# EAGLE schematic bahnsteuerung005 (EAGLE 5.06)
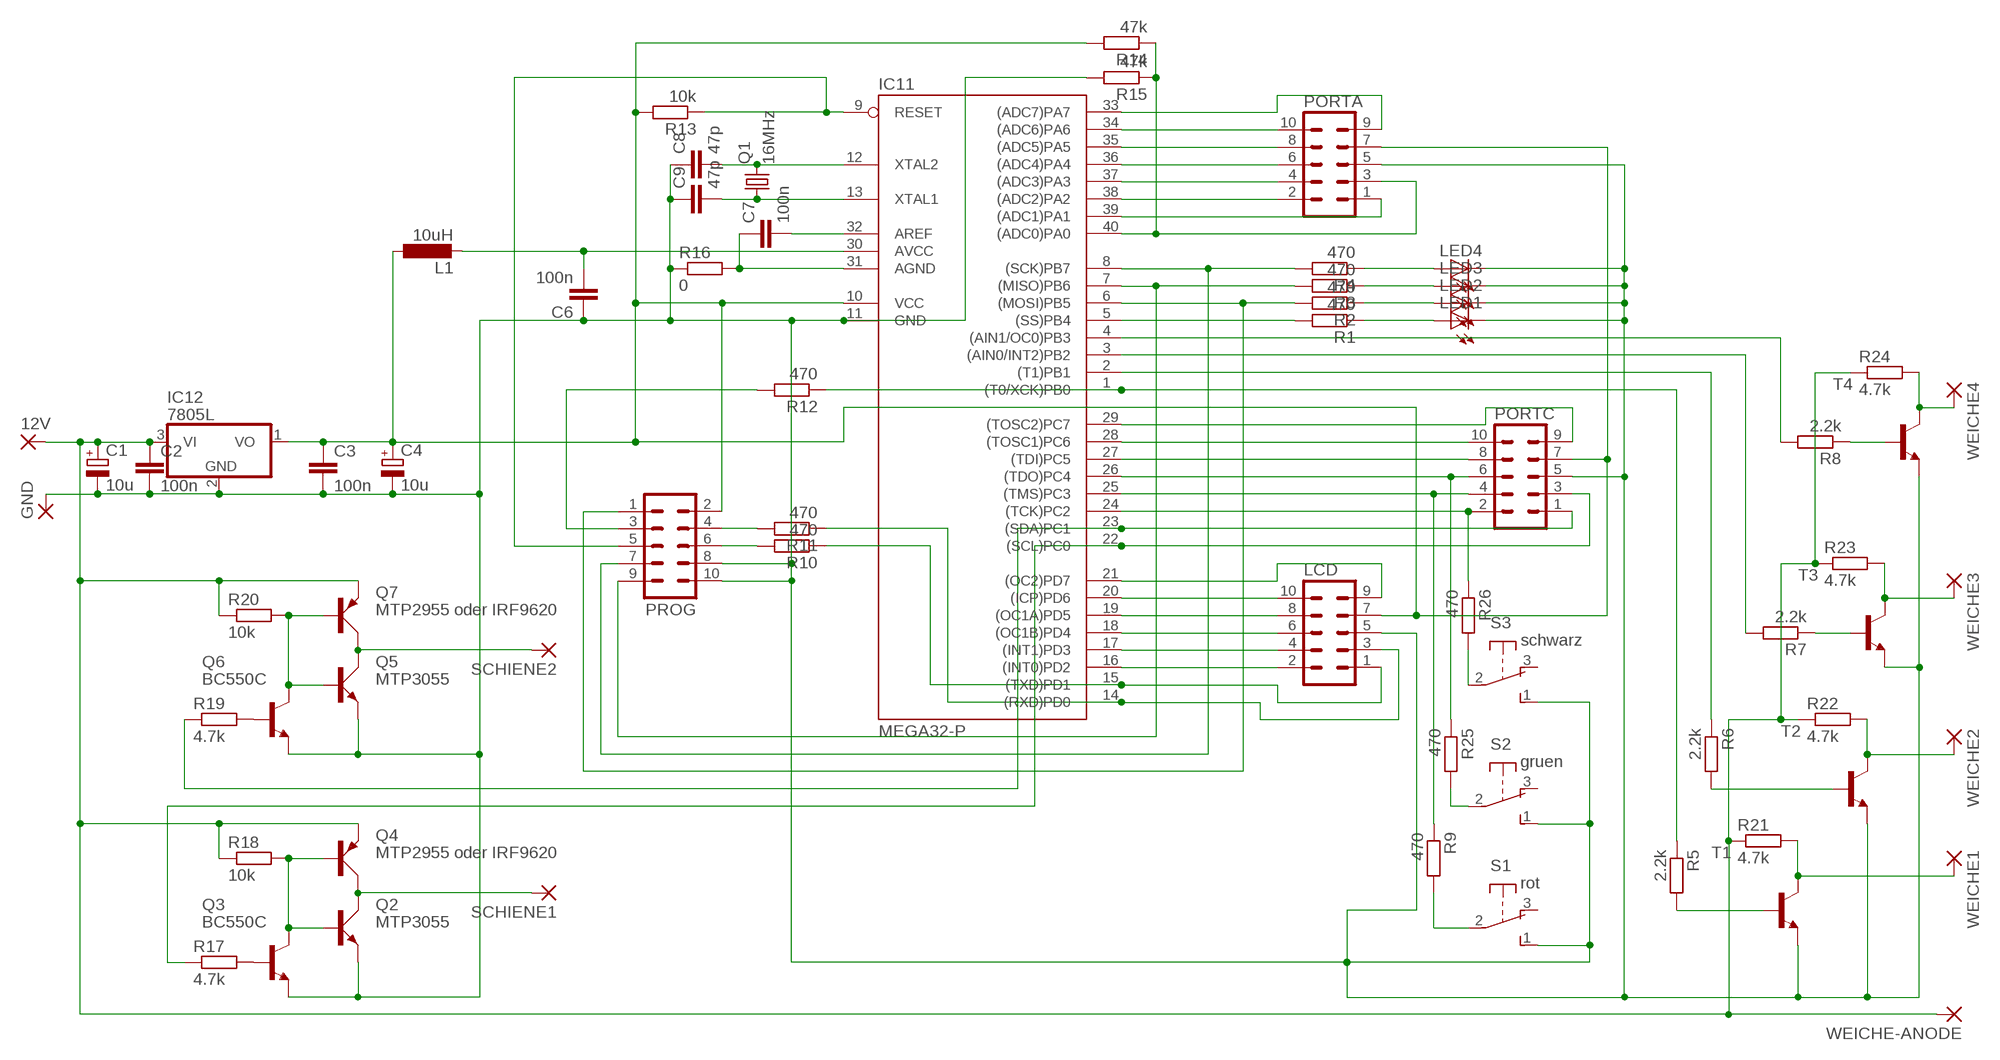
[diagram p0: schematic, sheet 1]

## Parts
12V  1,6/0,8  [1,6/0,8]
C1  10u  CPOL-EUE2.5-5  [E2,5-5]
C2  100n  C5/2.5  [C5B2.5]
C3  100n  C5/2.5  [C5B2.5]
C4  10u  CPOL-EUE2.5-5  [E2,5-5]
C6  100n  C5/2.5  [C5B2.5]
C7  100n  C2.5/2  [C2.5-2]
C8  47p  C2.5/2  [C2.5-2]
C9  47p  C2.5/2  [C2.5-2]
GND  1,6/0,8  [1,6/0,8]
IC11  MEGA32-P  [DIL40]
IC12  7805L  [TO92]
L1  10uH  L-EU0204/7  [0204/7@1]
LCD  ML10  [ML10]
LED1  LED3MM  [LED3MM]
LED2  LED3MM  [LED3MM]
LED3  LED3MM  [LED3MM]
LED4  LED3MM  [LED3MM]
PORTA  ML10  [ML10]
PORTC  ML10  [ML10]
PROG  ML10  [ML10]
Q1  16MHz  CRYTALHC49U-V  [HC49U-V]
Q2  MTP3055  MJE3055  [TO220AV]
Q3  BC550C  [TO92-EBC]
Q4  MTP2955 oder IRF9620  MJE2955  [TO220AV@1]
Q5  MTP3055  MJE3055  [TO220AV]
Q6  BC550C  [TO92-EBC]
Q7  MTP2955 oder IRF9620  MJE2955  [TO220AV@1]
R1  470  R-EU_0204/7  [0204/7]
R2  470  R-EU_0204/7  [0204/7]
R3  470  R-EU_0204/7  [0204/7]
R4  470  R-EU_0204/7  [0204/7]
R5  2.2k  R-EU_0204/7  [0204/7]
R6  2.2k  R-EU_0204/7  [0204/7]
R7  2.2k  R-EU_0204/7  [0204/7]
R8  2.2k  R-EU_0204/7  [0204/7]
R9  470  R-EU_0204/7  [0204/7]
R10  470  R-EU_0204/7  [0204/7]
R11  470  R-EU_0204/7  [0204/7]
R12  470  R-EU_0204/7  [0204/7]
R13  10k  R-EU_0204/7  [0204/7]
R14  47k  R-EU_0204/7  [0204/7]
R15  47k  R-EU_0204/7  [0204/7]
R16  0  R-EU_0204/2V  [0204V]
R17  4.7k  R-EU_0204/2V  [0204V]
R18  10k  R-EU_0204/7  [0204/7]
R19  4.7k  R-EU_0204/2V  [0204V]
R20  10k  R-EU_0204/7  [0204/7]
R21  4.7k  R-EU_0204/2V  [0204V]
R22  4.7k  R-EU_0204/2V  [0204V]
R23  4.7k  R-EU_0204/2V  [0204V]
R24  4.7k  R-EU_0204/2V  [0204V]
R25  470  R-EU_0204/7  [0204/7]
R26  470  R-EU_0204/7  [0204/7]
S1  rot  9077-1  [9077-1]
S2  gruen  9077-1  [9077-1]
S3  schwarz  9077-1  [9077-1]
SCHIENE1  1,6/0,8  [1,6/0,8]
SCHIENE2  1,6/0,8  [1,6/0,8]
T1  -NPN-TO220V  [TO220V]
T2  -NPN-TO220V  [TO220V]
T3  -NPN-TO220V  [TO220V]
T4  -NPN-TO220V  [TO220V]
WEICHE1  1,6/0,8  [1,6/0,8]
WEICHE2  1,6/0,8  [1,6/0,8]
WEICHE3  1,6/0,8  [1,6/0,8]
WEICHE4  1,6/0,8  [1,6/0,8]
WEICHE-ANODE  1,6/0,8  [1,6/0,8]

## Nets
AGND [mitteldick]: C7.1 IC11.31(AGND) R16.2
AREF [mitteldick]: C7.2 IC11.32(AREF)
AVCC [mitteldick]: C6.2 IC11.30(AVCC) L1.2
GND [mitteldick]: C1.- C2.2 C3.2 C4.- C6.1 C8.1 C9.1 GND.1(P) IC11.11(GND) IC12.2(GND) LCD.5 LED1.K(C) LED2.K(C) LED3.K(C) LED4.K(C) PORTA.5 PORTC.5 PROG.8 PROG.10 Q2.E Q3.E Q5.E Q6.E R15.2 R16.1 S1.1(S) S2.1(S) S3.1(S) T1.3(E) T2.3(E) T3.3(E) T4.3(E)
N$1: IC11.22((SCL)PC0) PORTC.3 R17.1
N$2: IC11.23((SDA)PC1) PORTC.1 R19.1
N$3: R8.1 T4.1(B)
N$4: IC11.4((AIN1/OC0)PB3) R8.2
N$5: R24.2 T4.2(C) WEICHE4.1(P)
N$6: IC11.5((SS)PB4) R1.2
N$7: LED1.A R1.1
N$8: LED2.A R2.1
N$9: LED3.A R3.1
N$10: LED4.A R4.1
N$11 [mitteldick]: IC11.16((INT0)PD2) LCD.2
N$12 [mitteldick]: IC11.17((INT1)PD3) LCD.4
N$13 [mitteldick]: IC11.18((OC1B)PD4) LCD.6
N$14 [mitteldick]: IC11.19((OC1A)PD5) LCD.8
N$15 [mitteldick]: IC11.20((ICP)PD6) LCD.10
N$16 [mitteldick]: IC11.21((OC2)PD7) LCD.9
N$17 [mitteldick]: IC11.25((TMS)PC3) PORTC.4 R9.1
N$18 [mitteldick]: IC11.26((TDO)PC4) PORTC.6 R25.1
N$19 [mitteldick]: IC11.27((TDI)PC5) PORTC.8
N$20 [mitteldick]: IC11.28((TOSC1)PC6) PORTC.10
N$21 [mitteldick]: IC11.29((TOSC2)PC7) PORTC.9
N$22 [mitteldick]: IC11.39((ADC1)PA1) PORTA.1
N$23 [mitteldick]: IC11.38((ADC2)PA2) PORTA.2
N$24 [mitteldick]: IC11.37((ADC3)PA3) PORTA.4
N$25 [mitteldick]: IC11.36((ADC4)PA4) PORTA.6
N$26 [mitteldick]: IC11.35((ADC5)PA5) PORTA.8
N$27 [mitteldick]: IC11.34((ADC6)PA6) PORTA.10
N$28 [mitteldick]: IC11.33((ADC7)PA7) PORTA.9
N$30: Q6.B R19.2
N$31: Q3.B R17.2
N$32: Q2.C Q4.C SCHIENE1.1(P)
N$33: R25.2 S2.2(P)
N$34: Q2.B Q3.C Q4.B R18.2
N$35: Q5.C Q7.C SCHIENE2.1(P)
N$36: R9.2 S1.2(P)
N$37: Q5.B Q6.C Q7.B R20.2
N$38: R26.2 S3.2(P)
N$122: IC11.40((ADC0)PA0) PORTA.3 R14.1 R15.1
N$135: IC11.6((MOSI)PB5) PROG.1 R2.2
N$136: IC11.7((MISO)PB6) PROG.9 R3.2
N$147: IC11.14((RXD)PD0) LCD.3 R11.1
N$149: R7.1 T3.1(B)
N$150: IC11.1((T0/XCK)PB0) R5.1 R12.1
N$152: C8.2 IC11.12(XTAL2) Q1.2
N$153: C9.2 IC11.13(XTAL1) Q1.1
N$156: IC11.9(RESET) PROG.5 R13.1
N$157: PROG.4 R11.2
N$158: PROG.6 R10.2
N$159: PROG.3 R12.2
N$160: IC11.24((TCK)PC2) PORTC.2 R26.1
N$161: IC11.15((TXD)PD1) LCD.1 R10.1
N$164: IC11.3((AIN0/INT2)PB2) R7.2
N$166: IC11.2((T1)PB1) R6.1
N$167: R5.2 T1.1(B)
N$168: R6.2 T2.1(B)
N$170: IC11.8((SCK)PB7) PROG.7 R4.2
N$172 [mitteldick]: R21.2 T1.2(C) WEICHE1.1(P)
N$173 [mitteldick]: R22.2 T2.2(C) WEICHE2.1(P)
N$174 [mitteldick]: R23.2 T3.2(C) WEICHE3.1(P)
VCC [mitteldick]: C3.1 C4.+ IC11.10(VCC) IC12.1(VO) L1.1 LCD.7 PORTA.7 PORTC.7 PROG.2 R13.2 R14.2
VCC1 [mitteldick]: 12V.1(P) C1.+ C2.1 IC12.3(VI) Q4.E Q7.E R18.1 R20.1 R21.1 R22.1 R23.1 R24.1 WEICHE-ANODE.1(P)
Unconnected: S1.3(O) S2.3(O) S3.3(O)

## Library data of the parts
12V GND SCHIENE1 SCHIENE2 WEICHE1-WEICHE4 WEICHE-ANODE = wirepad:1,6/0,8: THROUGH-HOLE PAD
C1 C4 = rcl:CPOL-EU: POLARIZED CAPACITOR, European symbol
C2 C3 C6-C9 = capacitor-wima:C: CAPACITOR
IC11 = atmel:MEGA32-P: MICROCONTROLLER 32 Kbytes FLASH 2 Kbytes SRAM 1 Kbytes EEPROM USART 8-channel 10 bit ADC Source: www.atmel.com .. doc2503.pdf
IC12 = linear:78*: Positive VOLTAGE REGULATOR Source: http://cache.national.com/ds/LM/LM78L05.pdf http://www.fairchildsemi.com/ds/LM/LM7805.pdf
L1 = rcl:L-EU: INDUCTOR, European symbol
LCD PORTA PORTC PROG = con-harting-ml:ML10: HARTING
LED1-LED4 = led:LED: LED
Q1 = crystal:CRYTAL: CRYSTAL
Q2 Q5 = transistor-power:MJE3055: NPN TRANSISTOR
Q3 Q6 = transistor-npn:BC550*: NPN Transistor
Q4 Q7 = transistor-power:MJE2955: PNP TRANSISTOR
R1-R26 = rcl:R-EU_: RESISTOR, European symbol
S1-S3 = switch-misc:9077-1: MARQUARDT SWITCH
T1-T4 = transistor:*-NPN-: NPN Transistror

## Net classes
1 dick: width 1.016 mm, clearance 0.61 mm
2 mitteldick: width 0.762 mm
